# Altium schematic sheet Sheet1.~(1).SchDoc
size A4; SheetNumber: 1; SheetTotal: 1
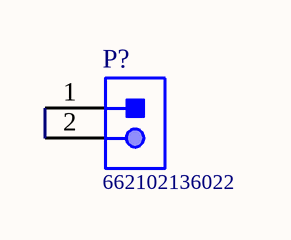
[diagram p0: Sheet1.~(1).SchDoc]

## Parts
P?  662102136022  [662102136022]

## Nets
NetP?_1: P?.1 P?.2

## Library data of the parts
P? = CMP-1502-00472-1: SMT Male Header WR-MPC3, with Snap-in Plastic Pegs, Right Angled, Single Row, pitch 3 mm, 2 pins; Manufacturer: Wurth Elektronik; Working Voltage: 250VAC; Contact Resistance: 10mOhm; Pitch: 3mm; Pin Number: 2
